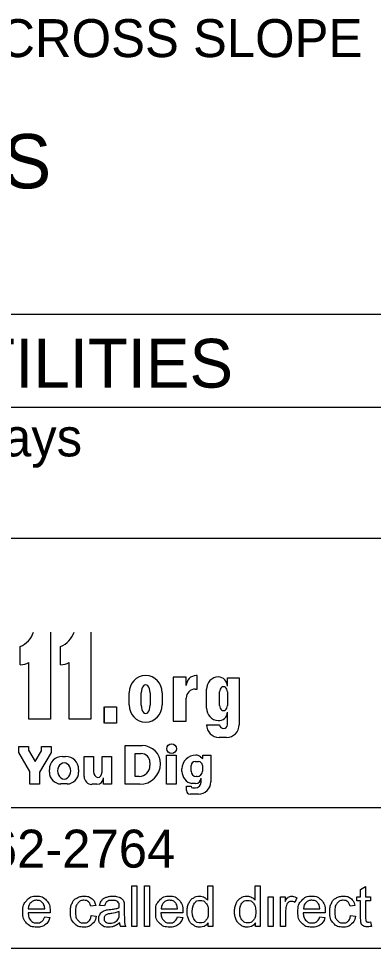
# Model space of a CAD drawing. Extents: x -3.6 to 34, y 0 to 32.8.
# Drawn here: x 4.831 to 6.139, y 1.879 to 5.307 of the extents above; entities that cross this region are included whole.
import ezdxf

# ---------------------------------------------------------------- set-up
doc = ezdxf.new("R2010")
doc.units = 0
doc.layers.add('SH_Data', color=7, linetype='Continuous')
doc.layers.add('SH_Text', color=7, linetype='Continuous')

msp = doc.modelspace()

# ---------------------------------------------------------------- linework, layer by layer
at = {"layer": 'SH_Data'}
for p, q in [((6.6275, 4.216), (2.3775, 4.216)), ((2.3775, 3.8744), (6.6275, 3.8744)), ((2.3775, 3.391), (6.6275, 3.391)), ((6.6275, 2.3964), (2.3775, 2.3964)), ((6.6275, 1.8785), (2.3775, 1.8785))]:
    msp.add_line(p, q, dxfattribs=at)
at = {"layer": 'SH_Text'}
for p, q in [((4.9487, 3.0444), (4.9487, 2.7244)), ((5.0975, 3.0444), (5.0975, 2.7244)), ((4.8371, 2.9237), (4.8371, 2.9919)), ((4.9859, 2.9237), (4.9859, 2.9919)), ((4.8694, 2.7244), (4.8694, 2.933)), ((5.0182, 2.7244), (5.0182, 2.933)), ((5.49, 2.8844), (5.486, 2.8844)), ((5.49, 2.8346), (5.49, 2.8844)), ((5.4493, 2.8793), (5.4005, 2.8793)), ((5.4005, 2.8793), (5.4005, 2.7163)), ((5.4493, 2.8477), (5.4493, 2.8793)), ((5.6009, 2.8451), (5.6009, 2.8761)), ((5.6009, 2.8761), (5.6444, 2.8761)), ((5.6444, 2.8761), (5.6444, 2.7033)), ((5.2385, 2.7762), (5.2385, 2.8215)), ((5.2835, 2.7754), (5.2835, 2.8215)), ((5.3157, 2.8215), (5.3157, 2.7754)), ((5.3606, 2.8215), (5.3606, 2.7762)), ((5.4823, 2.8346), (5.49, 2.8346)), ((5.5239, 2.7647), (5.5239, 2.8343)), ((5.5723, 2.774), (5.5723, 2.825)), ((5.6009, 2.825), (5.6009, 2.774)), ((5.4493, 2.7163), (5.4493, 2.8016)), ((5.1456, 2.7694), (5.1456, 2.7094)), ((5.6009, 2.7033), (5.6009, 2.7496)), ((4.9487, 2.7244), (4.8694, 2.7244)), ((5.0975, 2.7244), (5.0182, 2.7244)), ((5.4005, 2.7163), (5.4493, 2.7163)), ((5.5239, 2.7033), (5.5723, 2.7033)), ((5.5977, 2.6565), (5.5707, 2.6565)), ((4.8319, 2.6227), (4.8677, 2.6227)), ((4.8319, 2.6012), (4.8319, 2.6227)), ((4.8677, 2.6227), (4.8677, 2.6091)), ((4.8677, 2.6091), (4.8918, 2.5677)), ((4.8918, 2.5677), (4.9151, 2.6076)), ((4.9151, 2.6076), (4.9151, 2.6227)), ((4.9151, 2.6227), (4.9509, 2.6227)), ((4.9509, 2.6227), (4.9509, 2.6012)), ((5.2243, 2.6263), (5.2866, 2.6263)), ((5.2243, 2.4836), (5.2243, 2.6263)), ((4.8732, 2.5303), (4.8319, 2.6012)), ((4.9509, 2.6012), (4.9088, 2.5289)), ((4.9925, 2.5865), (5.0047, 2.5865)), ((5.0727, 2.5865), (5.1075, 2.5865)), ((5.0727, 2.5119), (5.0727, 2.5865)), ((5.1075, 2.5865), (5.1075, 2.5312)), ((5.1388, 2.5295), (5.1388, 2.5865)), ((5.1388, 2.5865), (5.1736, 2.5865)), ((5.1736, 2.5865), (5.1736, 2.4836)), ((5.2603, 2.513), (5.2603, 2.597)), ((5.2603, 2.597), (5.2828, 2.597)), ((5.377, 2.5907), (5.4126, 2.5907)), ((5.377, 2.4836), (5.377, 2.5907)), ((5.4126, 2.5907), (5.4126, 2.4836)), ((5.5021, 2.5851), (5.5107, 2.5784)), ((5.5107, 2.591), (5.5395, 2.591)), ((5.5107, 2.5784), (5.5107, 2.591)), ((5.5107, 2.591), (5.5395, 2.591)), ((5.5395, 2.591), (5.5395, 2.4924)), ((4.9447, 2.5279), (4.9447, 2.5387)), ((5.0525, 2.5387), (5.0525, 2.5279)), ((5.3154, 2.5643), (5.3154, 2.5525)), ((5.4335, 2.531), (5.4335, 2.5411)), ((5.467, 2.5318), (5.467, 2.553)), ((5.4816, 2.5677), (5.4944, 2.5677)), ((5.509, 2.553), (5.509, 2.5318)), ((4.8732, 2.4836), (4.8732, 2.5303)), ((4.9088, 2.5289), (4.9088, 2.4836)), ((5.1439, 2.4836), (5.1439, 2.5076)), ((5.2759, 2.513), (5.2603, 2.513)), ((5.4897, 2.5125), (5.4863, 2.5125)), ((5.5039, 2.4914), (5.5039, 2.5068)), ((4.9088, 2.4836), (4.8732, 2.4836)), ((5.0097, 2.4851), (4.9875, 2.4851)), ((5.1199, 2.4836), (5.1011, 2.4836)), ((5.1736, 2.4836), (5.1439, 2.4836)), ((5.2779, 2.4836), (5.2243, 2.4836)), ((5.4126, 2.4836), (5.377, 2.4836)), ((5.45, 2.4602), (5.45, 2.4773)), ((5.45, 2.4773), (5.467, 2.4773)), ((5.4835, 2.4863), (5.4698, 2.4863)), ((5.4738, 2.4702), (5.4827, 2.4702)), ((5.4942, 2.4471), (5.4631, 2.4471))]:
    msp.add_line(p, q, dxfattribs=at)
msp.add_lwpolyline([(5.148, 2.7694), (5.1921, 2.7694), (5.1921, 2.7094), (5.148, 2.7094)], close=True, dxfattribs=at)
for points in [[(5.2491, 1.9596), (5.2491, 2.1098), (5.2675, 2.1098), (5.2675, 1.9596), (5.2491, 1.9596)], [(5.2956, 1.9596), (5.2956, 2.1098), (5.3141, 2.1098), (5.3141, 1.9596), (5.2956, 1.9596)], [(5.5285, 2.056), (5.5285, 2.1098), (5.5469, 2.1098), (5.5469, 1.9596), (5.5299, 1.9596)], [(5.7034, 2.056), (5.7034, 2.1098), (5.7218, 2.1098), (5.7218, 1.9596), (5.7048, 1.9596)], [(6.092, 1.9915), (6.092, 2.0542), (6.0784, 2.0542), (6.0784, 2.0685), (6.092, 2.0685), (6.092, 2.0954), (6.1105, 2.1065), (6.1105, 2.0685), (6.1289, 2.0685), (6.1289, 2.0542), (6.1105, 2.0542), (6.1105, 1.9904)], [(5.7509, 1.9596), (5.7509, 2.0685), (5.7693, 2.0685), (5.7693, 1.9596), (5.7509, 1.9596)], [(5.7971, 1.9596), (5.7971, 2.0685), (5.8137, 2.0685), (5.8137, 2.052)], [(5.8562, 2.065), (5.8497, 2.0479)], [(4.8669, 2.0244), (4.9277, 2.0244)], [(5.1154, 2.0364), (5.0974, 2.0337)], [(5.1479, 2.0349), (5.1298, 2.0373)], [(5.2209, 2.0298), (5.2209, 2.0052)], [(5.3565, 2.0244), (5.4173, 2.0244)], [(5.881, 2.0244), (5.9418, 2.0244)], [(6.0712, 2.0364), (6.0532, 2.0337)], [(4.947, 2.0093), (4.8659, 2.0093)], [(4.9275, 1.9948), (4.9465, 1.9924)], [(5.099, 1.9995), (5.1171, 1.9971)], [(5.2023, 2.0075), (5.2024, 2.0142)], [(5.4366, 2.0093), (5.3555, 2.0093)], [(5.4171, 1.9948), (5.4361, 1.9924)], [(5.8155, 2.0166), (5.8155, 1.9596), (5.7971, 1.9596)], [(5.9611, 2.0093), (5.88, 2.0093)], [(5.9416, 1.9948), (5.9606, 1.9924)], [(6.0548, 1.9995), (6.0729, 1.9971)], [(5.2267, 1.9596), (5.2075, 1.9596)], [(5.5299, 1.9596), (5.5299, 1.9734)], [(5.7048, 1.9596), (5.7048, 1.9734)], [(6.1289, 1.9761), (6.1315, 1.9598)]]:
    msp.add_lwpolyline(points, dxfattribs=at)
msp.add_circle((5.3952, 2.615), 0.0177, dxfattribs=at)
for centre, radius, start, end in [((4.8031, 3.0736), 0.0885, 292.5572, 340.7355), ((4.952, 3.0736), 0.0885, 292.5572, 340.7355), ((4.8291, 3.0118), 0.0885, 275.1733, 297.0931), ((4.9779, 3.0118), 0.0885, 275.1733, 297.0931), ((5.3024, 2.8215), 0.064, 92.5886, 180), ((5.2967, 2.8215), 0.064, 0, 87.4114), ((5.486, 2.8477), 0.0367, 90, 180), ((5.5698, 2.8343), 0.0459, 92.6865, 180), ((5.5658, 2.8451), 0.0351, 0, 86.9262), ((5.4823, 2.8016), 0.033, 90, 180), ((5.3024, 2.7762), 0.064, 180, 267.4114), ((5.2967, 2.7762), 0.064, 272.5886, 0), ((5.5702, 2.7647), 0.0463, 180, 265.7132), ((5.5696, 2.7496), 0.0313, 264.7825, 0), ((5.5707, 2.7033), 0.0468, 180, 270), ((5.5977, 2.7033), 0.0468, 270, 0), ((5.2866, 2.5581), 0.0682, 0.9944, 90), ((4.9925, 2.5387), 0.0478, 90, 180), ((5.0047, 2.5387), 0.0478, 0, 90), ((5.2828, 2.5643), 0.0327, 0, 90), ((5.4834, 2.5411), 0.0499, 89.0934, 180), ((5.4848, 2.5627), 0.0283, 52.1415, 91.2046), ((5.2759, 2.5525), 0.0395, 270, 0), ((5.2779, 2.5605), 0.0769, 270, 359.0635), ((5.4816, 2.553), 0.0146, 90, 180), ((5.4944, 2.553), 0.0146, 0, 90), ((4.9875, 2.5279), 0.0428, 180, 270), ((5.0097, 2.5279), 0.0428, 270, 0), ((5.1011, 2.5119), 0.0284, 180, 270), ((5.1199, 2.5076), 0.024, 270, 0), ((5.4791, 2.531), 0.0457, 180, 258.2203), ((5.4863, 2.5318), 0.0193, 180, 270), ((5.4835, 2.5067), 0.0203, 270, 0), ((5.4897, 2.5318), 0.0193, 270, 0), ((5.4738, 2.4771), 0.00682, 180, 270), ((5.4827, 2.4914), 0.0212, 270, 0), ((5.4942, 2.4924), 0.0453, 270, 0), ((5.4631, 2.4602), 0.0131, 180, 270)]:
    msp.add_arc(centre, radius, start, end, dxfattribs=at)
for centre, major_axis, ratio, start_param, end_param in [((5.2996, 2.8215), (0, 0.0291), 0.553236, 4.712389, 7.853982), ((5.5866, 2.825), (0, 0.0184), 0.777179, 4.712389, 7.853982), ((5.2996, 2.7754), (0, 0.0308), 0.522014, 1.570796, 4.712389), ((5.5866, 2.774), (0, 0.0184), 0.777179, 1.570796, 4.712389), ((5.5866, 2.7033), (0.0143, 0), 0.959012, 3.141593, 6.283185), ((4.9991, 2.5333), (0, 0.029), 0.832186, 4.712389, 7.853982), ((4.9991, 2.5333), (0, 0.0302), 0.797287, 1.570796, 4.712389), ((5.1231, 2.5319), (-0.0011, 0.0231), 0.679042, 1.570796, 4.575961)]:
    msp.add_ellipse(centre, major_axis=major_axis, ratio=ratio, start_param=start_param, end_param=end_param, dxfattribs=at)
for points, degree in [([(4.9465, 1.9924), (4.942, 1.9757), (4.9298, 1.9665), (4.9177, 1.9572), (4.8987, 1.9572), (4.8749, 1.9572), (4.8609, 1.9719), (4.8469, 1.9866), (4.8469, 2.0131), (4.8469, 2.0406), (4.861, 2.0557), (4.8752, 2.0709), (4.8977, 2.0709), (4.9195, 2.0709), (4.9333, 2.056), (4.9471, 2.0412), (4.9471, 2.0142), (4.9471, 2.0126), (4.947, 2.0093)], 3), ([(5.1171, 1.9971), (5.1141, 1.9784), (5.1019, 1.9678), (5.0896, 1.9572), (5.0718, 1.9572), (5.0495, 1.9572), (5.0359, 1.9718), (5.0223, 1.9864), (5.0223, 2.0136), (5.0223, 2.0313), (5.0282, 2.0445), (5.034, 2.0577), (5.046, 2.0643), (5.0579, 2.0709), (5.0719, 2.0709), (5.0897, 2.0709), (5.1009, 2.0619), (5.1122, 2.0529), (5.1154, 2.0364)], 3), ([(5.1298, 2.0373), (5.1323, 2.0489), (5.1379, 2.0561), (5.1435, 2.0632), (5.1542, 2.067), (5.1648, 2.0709), (5.1788, 2.0709), (5.1928, 2.0709), (5.2015, 2.0676), (5.2102, 2.0643), (5.2142, 2.0593), (5.2183, 2.0544), (5.22, 2.0468), (5.2209, 2.0421), (5.2209, 2.0298)], 3), ([(5.4361, 1.9924), (5.4316, 1.9757), (5.4194, 1.9665), (5.4072, 1.9572), (5.3883, 1.9572), (5.3644, 1.9572), (5.3505, 1.9719), (5.3365, 1.9866), (5.3365, 2.0131), (5.3365, 2.0406), (5.3506, 2.0557), (5.3648, 2.0709), (5.3873, 2.0709), (5.4091, 2.0709), (5.4229, 2.056), (5.4367, 2.0412), (5.4367, 2.0142), (5.4367, 2.0126), (5.4366, 2.0093)], 3), ([(5.5299, 1.9734), (5.5195, 1.9572), (5.4995, 1.9572), (5.4865, 1.9572), (5.4755, 1.9644), (5.4646, 1.9716), (5.4586, 1.9844), (5.4526, 1.9973), (5.4526, 2.014), (5.4526, 2.0302), (5.4581, 2.0435), (5.4635, 2.0568), (5.4743, 2.0638), (5.4852, 2.0709), (5.4986, 2.0709), (5.5084, 2.0709), (5.516, 2.0667), (5.5237, 2.0626), (5.5285, 2.056)], 3), ([(5.7048, 1.9734), (5.6944, 1.9572), (5.6743, 1.9572), (5.6613, 1.9572), (5.6504, 1.9644), (5.6395, 1.9716), (5.6335, 1.9844), (5.6275, 1.9973), (5.6275, 2.014), (5.6275, 2.0302), (5.6329, 2.0435), (5.6384, 2.0568), (5.6492, 2.0638), (5.66, 2.0709), (5.6734, 2.0709), (5.6832, 2.0709), (5.6909, 2.0667), (5.6986, 2.0626), (5.7034, 2.056)], 3), ([(5.8137, 2.052), (5.8201, 2.0635), (5.8254, 2.0672), (5.8308, 2.0709), (5.8372, 2.0709), (5.8466, 2.0709), (5.8562, 2.065)], 3), ([(5.9606, 1.9924), (5.9561, 1.9757), (5.9439, 1.9665), (5.9317, 1.9572), (5.9128, 1.9572), (5.8889, 1.9572), (5.875, 1.9719), (5.861, 1.9866), (5.861, 2.0131), (5.861, 2.0406), (5.8751, 2.0557), (5.8892, 2.0709), (5.9118, 2.0709), (5.9336, 2.0709), (5.9474, 2.056), (5.9612, 2.0412), (5.9612, 2.0142), (5.9612, 2.0126), (5.9611, 2.0093)], 3), ([(6.0729, 1.9971), (6.07, 1.9784), (6.0577, 1.9678), (6.0455, 1.9572), (6.0277, 1.9572), (6.0053, 1.9572), (5.9917, 1.9718), (5.9782, 1.9864), (5.9782, 2.0136), (5.9782, 2.0313), (5.984, 2.0445), (5.9899, 2.0577), (6.0018, 2.0643), (6.0137, 2.0709), (6.0278, 2.0709), (6.0455, 2.0709), (6.0568, 2.0619), (6.068, 2.0529), (6.0712, 2.0364)], 3), ([(4.9277, 2.0244), (4.9265, 2.0382), (4.9207, 2.0451), (4.9119, 2.0558), (4.8979, 2.0558), (4.8852, 2.0558), (4.8765, 2.0472), (4.8678, 2.0387), (4.8669, 2.0244)], 3), ([(5.0974, 2.0337), (5.0949, 2.0447), (5.0884, 2.0502), (5.0819, 2.0558), (5.0726, 2.0558), (5.0587, 2.0558), (5.05, 2.0458), (5.0413, 2.0358), (5.0413, 2.0142), (5.0413, 1.9922), (5.0497, 1.9823), (5.0581, 1.9723), (5.0717, 1.9723), (5.0825, 1.9723), (5.0898, 1.979), (5.0971, 1.9856), (5.099, 1.9995)], 3), ([(5.2038, 1.973), (5.1936, 1.9644), (5.1841, 1.9608), (5.1746, 1.9572), (5.1638, 1.9572), (5.1458, 1.9572), (5.1362, 1.966), (5.1266, 1.9747), (5.1266, 1.9883), (5.1266, 1.9963), (5.1302, 2.0029), (5.1339, 2.0095), (5.1398, 2.0135), (5.1456, 2.0175), (5.153, 2.0195), (5.1584, 2.021), (5.1694, 2.0223), (5.1917, 2.025), (5.2023, 2.0287), (5.2024, 2.0325), (5.2024, 2.0335), (5.2024, 2.0448), (5.1971, 2.0494), (5.1901, 2.0557), (5.1762, 2.0557), (5.1632, 2.0557), (5.157, 2.0511), (5.1508, 2.0465), (5.1479, 2.0349)], 3), ([(5.4173, 2.0244), (5.4161, 2.0382), (5.4103, 2.0451), (5.4015, 2.0558), (5.3875, 2.0558), (5.3748, 2.0558), (5.3661, 2.0472), (5.3574, 2.0387), (5.3565, 2.0244)], 3), ([(5.4716, 2.0139), (5.4716, 1.993), (5.4805, 1.9827), (5.4893, 1.9723), (5.5012, 1.9723), (5.5133, 1.9723), (5.5218, 1.9822), (5.5302, 1.9921), (5.5302, 2.0124), (5.5302, 2.0348), (5.5216, 2.0452), (5.513, 2.0557), (5.5004, 2.0557), (5.4881, 2.0557), (5.4799, 2.0456), (5.4716, 2.0356), (5.4716, 2.0139)], 3), ([(5.6465, 2.0139), (5.6465, 1.993), (5.6553, 1.9827), (5.6641, 1.9723), (5.6761, 1.9723), (5.6882, 1.9723), (5.6967, 1.9822), (5.7051, 1.9921), (5.7051, 2.0124), (5.7051, 2.0348), (5.6965, 2.0452), (5.6879, 2.0557), (5.6753, 2.0557), (5.663, 2.0557), (5.6548, 2.0456), (5.6465, 2.0356), (5.6465, 2.0139)], 3), ([(5.8497, 2.0479), (5.843, 2.0519), (5.8363, 2.0519), (5.8302, 2.0519), (5.8255, 2.0482), (5.8207, 2.0446), (5.8186, 2.0381), (5.8155, 2.0283), (5.8155, 2.0166)], 3), ([(5.9418, 2.0244), (5.9405, 2.0382), (5.9348, 2.0451), (5.926, 2.0558), (5.912, 2.0558), (5.8993, 2.0558), (5.8906, 2.0472), (5.8819, 2.0387), (5.881, 2.0244)], 3), ([(6.0532, 2.0337), (6.0507, 2.0447), (6.0442, 2.0502), (6.0377, 2.0558), (6.0285, 2.0558), (6.0146, 2.0558), (6.0059, 2.0458), (5.9972, 2.0358), (5.9972, 2.0142), (5.9972, 1.9922), (6.0056, 1.9823), (6.014, 1.9723), (6.0275, 1.9723), (6.0384, 1.9723), (6.0456, 1.979), (6.0529, 1.9856), (6.0548, 1.9995)], 3), ([(4.8659, 2.0093), (4.8669, 1.9914), (4.876, 1.9819), (4.8852, 1.9723), (4.8988, 1.9723), (4.9089, 1.9723), (4.9161, 1.9777), (4.9233, 1.983), (4.9275, 1.9948)], 3), ([(5.2024, 2.0142), (5.1923, 2.0101), (5.1722, 2.0073), (5.1608, 2.0056), (5.1561, 2.0036), (5.1514, 2.0015), (5.1488, 1.9976), (5.1463, 1.9937), (5.1463, 1.9889), (5.1463, 1.9815), (5.1519, 1.9766), (5.1574, 1.9717), (5.1682, 1.9717), (5.1788, 1.9717), (5.1871, 1.9763), (5.1954, 1.981), (5.1993, 1.9891), (5.2023, 1.9953), (5.2023, 2.0075)], 3), ([(5.2209, 2.0052), (5.2209, 1.9795), (5.2221, 1.9727), (5.2233, 1.9659), (5.2267, 1.9596)], 3), ([(5.3555, 2.0093), (5.3565, 1.9914), (5.3656, 1.9819), (5.3748, 1.9723), (5.3884, 1.9723), (5.3985, 1.9723), (5.4057, 1.9777), (5.4129, 1.983), (5.4171, 1.9948)], 3), ([(5.88, 2.0093), (5.881, 1.9914), (5.8901, 1.9819), (5.8992, 1.9723), (5.9129, 1.9723), (5.923, 1.9723), (5.9302, 1.9777), (5.9374, 1.983), (5.9416, 1.9948)], 3), ([(6.1315, 1.9598), (6.1238, 1.9582), (6.1176, 1.9582), (6.1076, 1.9582), (6.1021, 1.9613), (6.0965, 1.9645), (6.0943, 1.9697), (6.092, 1.9749), (6.092, 1.9915)], 3), ([(6.1105, 1.9904), (6.1105, 1.9825), (6.1114, 1.9802), (6.1124, 1.978), (6.1146, 1.9767), (6.1168, 1.9753), (6.1209, 1.9753), (6.1239, 1.9753), (6.1289, 1.9761)], 3), ([(5.2075, 1.9596), (5.2047, 1.9654), (5.2038, 1.973)], 2)]:
    msp.add_open_spline(points, degree=degree, dxfattribs=at)

# ---------------------------------------------------------------- texts
for s, height, p in [('PAVEMENT CROSS SLOPE', 0.14, (3.6744, 5.1652)), ('ADA DESIGN WAIVERS', 0.2, (1.9944, 4.6814)), ('UNDERGROUND UTILITIES', 0.18, (2.5057, 3.9464)), ('Contact Two Working Days', 0.14, (2.7972, 3.6929)), ('OHIO811, 8-1-1, or 1-800-362-2764', 0.14, (2.422, 2.1763))]:
    msp.add_text(s, height=height, dxfattribs=at).set_placement(p)

doc.saveas('drawing.dxf')
